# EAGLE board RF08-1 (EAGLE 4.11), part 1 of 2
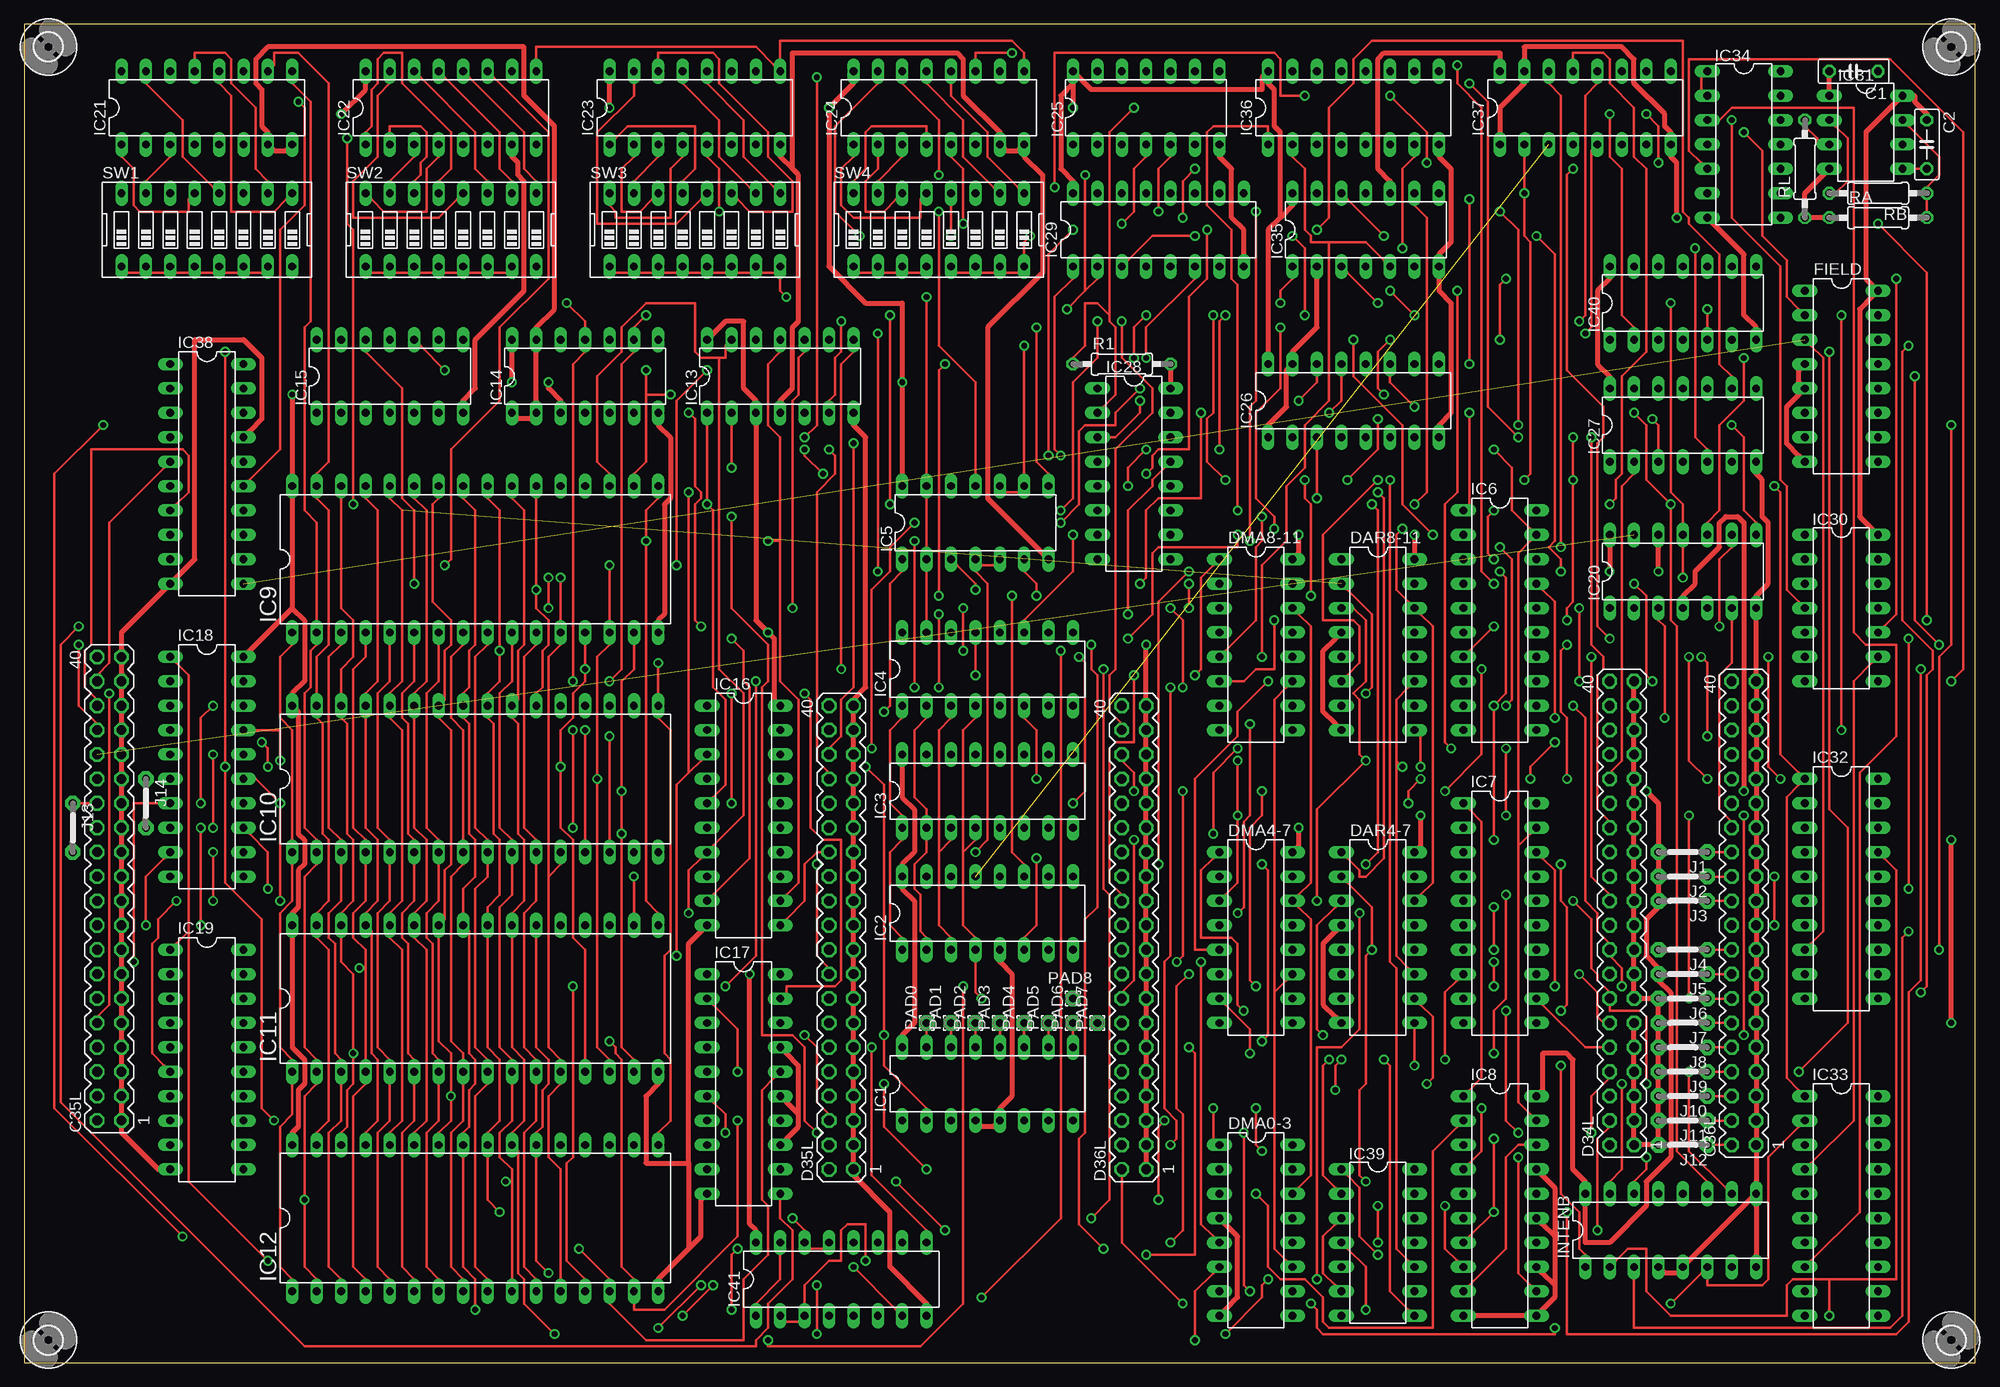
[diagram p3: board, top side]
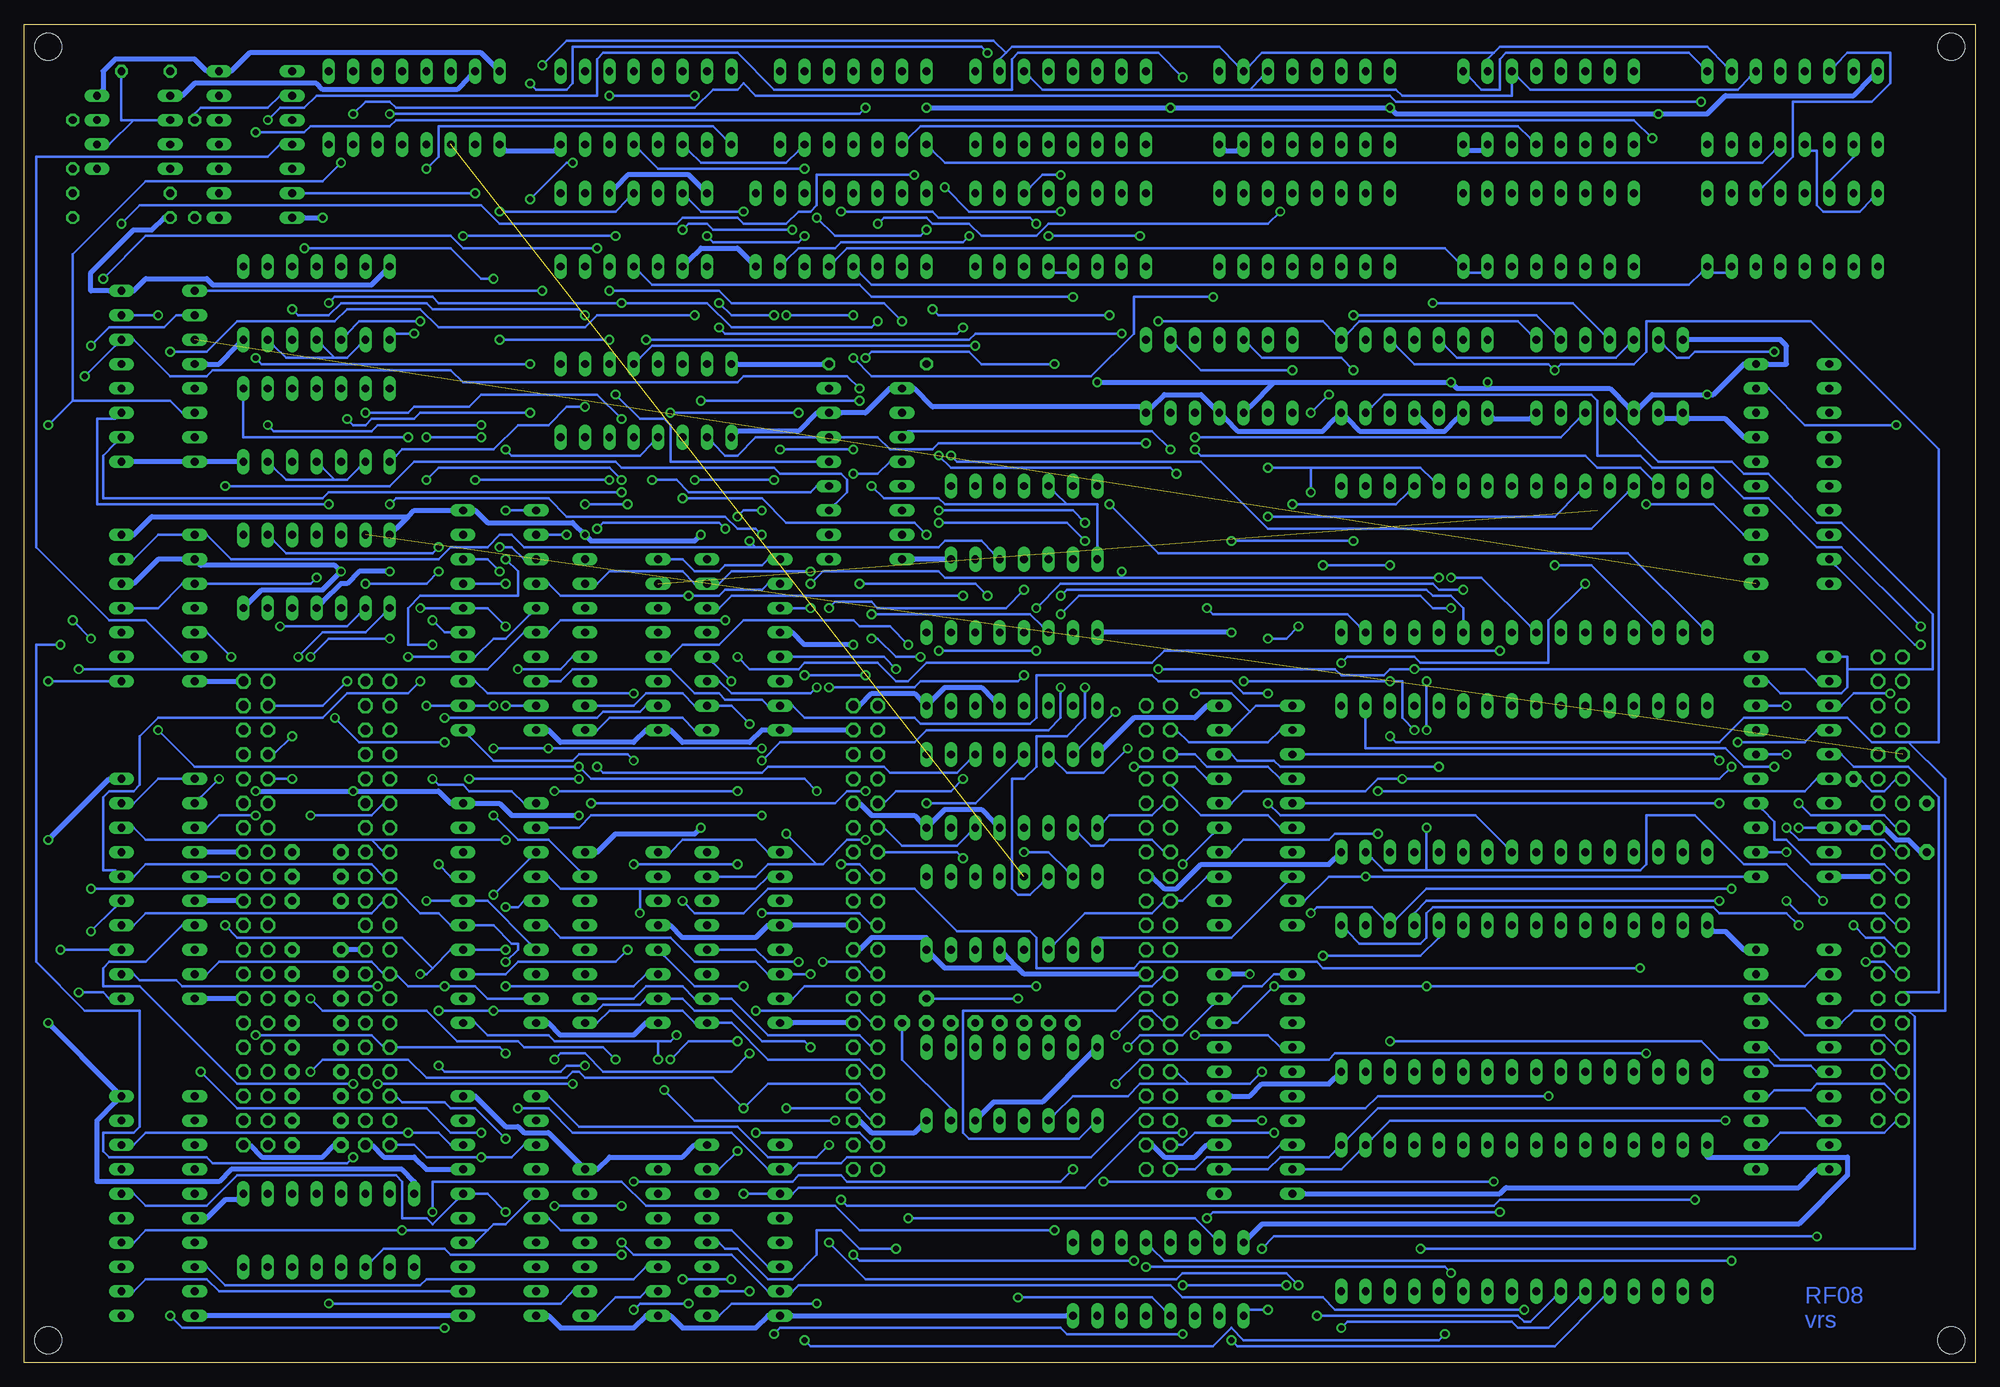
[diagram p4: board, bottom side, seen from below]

Size 203.18 x 139.37 mm. Coordinates in mm from the lower left corner, seen from the top.
Outline: 0,0 203.18,0 203.18,139.37 0,139.37 0,0
Copper layers (1*16): Top 0.035mm / dielectric 1.5mm / Bottom 0.035mm
Design rules "default": minimum track width 10mil, minimum drill 24mil, track to track 8mil, track to pad 8mil, pad to pad 8mil, via to via 8mil, smd to smd 8mil, copper to edge 40mil, drill to drill 8mil, minimum pad ring 10mil, minimum via ring 8mil, stop-mask expansion 4mil, vias tented up to drill 0mil, thermal gap 10mil
Net classes: 1 Power: width 0.508 mm

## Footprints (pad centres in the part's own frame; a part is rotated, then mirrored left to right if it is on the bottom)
C050-025X075 = drill 0.813 octagon: 1 -2.54,0; 2 2.54,0
MA20-2 = drill 1.016 octagon: 1 -24.13,-1.27; 2 -24.13,1.27; 3 -21.59,-1.27; 4 -21.59,1.27; 5 -19.05,-1.27; 6 -19.05,1.27; 7 -16.51,-1.27; 8 -16.51,1.27; 9 -13.97,-1.27; 10 -13.97,1.27; 11 -11.43,-1.27; 12 -11.43,1.27; 13 -8.89,-1.27; 14 -8.89,1.27; 15 -6.35,-1.27; 16 -6.35,1.27; 17 -3.81,-1.27; 18 -3.81,1.27; 19 -1.27,-1.27; 20 -1.27,1.27; 21 1.27,-1.27; 22 1.27,1.27; 23 3.81,-1.27; 24 3.81,1.27; 25 6.35,-1.27; 26 6.35,1.27; 27 8.89,-1.27; 28 8.89,1.27; 29 11.43,-1.27; 30 11.43,1.27; 31 13.97,-1.27; 32 13.97,1.27; 33 16.51,-1.27; 34 16.51,1.27; 35 19.05,-1.27; 36 19.05,1.27; 37 21.59,-1.27; 38 21.59,1.27; 39 24.13,-1.27; 40 24.13,1.27
DIL16 = drill 0.813 long: 1 -8.89,-3.81; 2 -6.35,-3.81; 3 -3.81,-3.81; 4 -1.27,-3.81; 5 1.27,-3.81; 6 3.81,-3.81; 7 6.35,-3.81; 8 8.89,-3.81; 9 8.89,3.81; 10 6.35,3.81; 11 3.81,3.81; 12 1.27,3.81; 13 -1.27,3.81; 14 -3.81,3.81; 15 -6.35,3.81; 16 -8.89,3.81
DIL14 = drill 0.813 long: 1 -7.62,-3.81; 2 -5.08,-3.81; 3 -2.54,-3.81; 4 0,-3.81; 5 2.54,-3.81; 6 5.08,-3.81; 7 7.62,-3.81; 8 7.62,3.81; 9 5.08,3.81; 10 2.54,3.81; 11 0,3.81; 12 -2.54,3.81; 13 -5.08,3.81; 14 -7.62,3.81
DIL20 = drill 0.813 long: 1 -11.43,-3.81; 2 -8.89,-3.81; 3 -6.35,-3.81; 4 -3.81,-3.81; 5 -1.27,-3.81; 6 1.27,-3.81; 7 3.81,-3.81; 8 6.35,-3.81; 9 8.89,-3.81; 10 11.43,-3.81; 11 11.43,3.81; 12 8.89,3.81; 13 6.35,3.81; 14 3.81,3.81; 15 1.27,3.81; 16 -1.27,3.81; 17 -3.81,3.81; 18 -6.35,3.81; 19 -8.89,3.81; 20 -11.43,3.81
DIL32 = drill 0.813 long: 1 -19.05,-7.62; 2 -16.51,-7.62; 3 -13.97,-7.62; 4 -11.43,-7.62; 5 -8.89,-7.62; 6 -6.35,-7.62; 7 -3.81,-7.62; 8 -1.27,-7.62; 9 1.27,-7.62; 10 3.81,-7.62; 11 6.35,-7.62; 12 8.89,-7.62; 13 11.43,-7.62; 14 13.97,-7.62; 15 16.51,-7.62; 16 19.05,-7.62; 17 19.05,7.62; 18 16.51,7.62; 19 13.97,7.62; 20 11.43,7.62; 21 8.89,7.62; 22 6.35,7.62; 23 3.81,7.62; 24 1.27,7.62; 25 -1.27,7.62; 26 -3.81,7.62; 27 -6.35,7.62; 28 -8.89,7.62; 29 -11.43,7.62; 30 -13.97,7.62; 31 -16.51,7.62; 32 -19.05,7.62
DIL08 = drill 0.813 long: 1 -3.81,-3.81; 2 -1.27,-3.81; 3 1.27,-3.81; 4 3.81,-3.81; 5 3.81,3.81; 6 1.27,3.81; 7 -1.27,3.81; 8 -3.81,3.81
05 = drill 0.813 pad 1.6 octagon: 1 -2.54,0; 2 2.54,0
1,6/0,8 = drill 0.813 pad 1.6 octagon: 1 0,0
0207/10 = drill 0.813 octagon: 1 -5.08,0; 2 5.08,0
EDG-08 = drill 0.813 long: 1 -8.89,-3.81; 2 -6.35,-3.81; 3 -3.81,-3.81; 4 -1.27,-3.81; 5 1.27,-3.81; 6 3.81,-3.81; 7 6.35,-3.81; 8 8.89,-3.81; 9 8.89,3.81; 10 6.35,3.81; 11 3.81,3.81; 12 1.27,3.81; 13 -1.27,3.81; 14 -3.81,3.81; 15 -6.35,3.81; 16 -8.89,3.81
2,8 = hole 2.8: 0,0

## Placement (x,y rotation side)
C1  .1uf  [C050-025X075]  190.5,134.46 180 top
C2  .1uf  [C050-025X075]  198.12,126.83 270 top
C35L  [MA20-2]  8.88,49.37 90 top
C36L  [MA20-2]  179.06,46.83 90 top
D34L  [MA20-2]  166.37,46.83 90 top
D35L  [MA20-2]  85.09,44.29 90 top
D36L  [MA20-2]  115.56,44.29 90 top
DAR4-7  74LS193N  [DIL16]  140.97,44.29 270 top
DAR8-11  74LS193N  [DIL16]  140.97,74.77 270 top
DMA0-3  74LS193N  [DIL16]  128.27,13.81 270 top
DMA4-7  74LS193N  [DIL16]  128.27,44.29 270 top
DMA8-11  74LS193N  [DIL16]  128.27,74.77 270 top
FIELD  74LS193N  [DIL16]  189.22,102.7 270 top
IC1  74S138N  [DIL16]  100.33,29.05 0 top
IC2  74S138N  [DIL16]  100.33,46.83 0 top
IC3  74S138N  [DIL16]  100.33,59.52 0 top
IC4  74S138N  [DIL16]  100.33,72.22 0 top
IC5  74LS00N  [DIL14]  99.06,87.46 0 top
IC6  74S240N  [DIL20]  153.66,77.3 270 top
IC7  74S240N  [DIL20]  153.66,46.83 270 top
IC8  74S240N  [DIL20]  153.66,16.35 270 top
IC9  628512  [DIL32]  46.98,83.65 0 top
IC10  628512  [DIL32]  46.98,60.8 0 top
IC11  628512  [DIL32]  46.98,37.94 0 top
IC12  628512  [DIL32]  46.98,15.08 0 top
IC13  74180N  [DIL14]  78.73,102.7 0 top
IC14  74180N  [DIL14]  58.41,102.7 0 top
IC15  74180N  [DIL14]  38.09,102.7 0 top
IC16  74LS244N  [DIL20]  74.93,56.98 270 top
IC17  74LS244N  [DIL20]  74.93,29.05 270 top
IC18  74S240N  [DIL20]  19.05,62.06 270 top
IC19  74S240N  [DIL20]  19.05,31.59 270 top
IC20  74S74N  [DIL14]  172.72,82.38 0 top
IC21  74LS151N  [DIL16]  19.05,130.65 0 top
IC22  74LS151N  [DIL16]  44.45,130.65 0 top
IC23  74LS151N  [DIL16]  69.84,130.65 0 top
IC24  74LS151N  [DIL16]  95.25,130.65 0 top
IC25  74LS20N  [DIL14]  116.84,130.65 0 top
IC26  74S139N  [DIL16]  138.43,100.16 0 top
IC27  7407N  [DIL14]  172.72,97.62 0 top
IC28  74S139N  [DIL16]  115.56,92.54 270 top
IC29  74LS139N  [DIL16]  118.11,117.94 0 top
IC30  74S74N  [DIL14]  189.22,78.57 270 top
IC31  LM555N  [DIL08]  191.77,128.11 270 top
IC32  74S240N  [DIL20]  189.22,49.37 270 top
IC33  74S240N  [DIL20]  189.22,16.35 270 top
IC34  74LS00N  [DIL14]  179.06,126.83 270 top
IC35  74S74N  [DIL14]  139.69,117.94 0 top
IC36  74S139N  [DIL16]  138.43,130.65 0 top
IC37  74LS139N  [DIL16]  162.56,130.65 0 top
IC38  74S240N  [DIL20]  19.05,92.54 270 top
IC39  74S03N  [DIL14]  140.97,12.54 270 top
IC40  7407N  [DIL14]  172.72,110.32 0 top
IC41  74LS139N  [DIL16]  85.09,8.73 0 top
INTENB  74LS193N  [DIL16]  171.44,13.81 0 top
J1  J5MM  [05]  172.72,53.18 180 top
J2  J5MM  [05]  172.72,50.63 180 top
J3  J5MM  [05]  172.72,48.09 180 top
J4  J5MM  [05]  172.72,43.02 180 top
J5  J5MM  [05]  172.72,40.48 180 top
J6  J5MM  [05]  172.72,37.94 180 top
J7  J5MM  [05]  172.72,35.4 180 top
J8  J5MM  [05]  172.72,32.86 180 top
J9  J5MM  [05]  172.72,30.32 180 top
J10  J5MM  [05]  172.72,27.78 180 top
J11  J5MM  [05]  172.72,25.23 180 top
J12  J5MM  [05]  172.72,22.7 180 top
J13  J5MM  [05]  5.08,55.72 270 top
J14  J5MM  [05]  12.69,58.26 270 top
PAD0  [1,6/0,8]  93.98,35.4 90 top
PAD1  [1,6/0,8]  96.52,35.4 90 top
PAD2  [1,6/0,8]  99.06,35.4 90 top
PAD3  [1,6/0,8]  101.59,35.4 90 top
PAD4  [1,6/0,8]  104.14,35.4 90 top
PAD5  [1,6/0,8]  106.68,35.4 90 top
PAD6  [1,6/0,8]  109.22,35.4 90 top
PAD7  [1,6/0,8]  111.76,35.4 90 top
PAD8  [1,6/0,8]  109.22,37.94 90 top
R1  4.7K  [0207/10]  114.3,103.97 0 top
RA  470K  [0207/10]  193.03,119.21 0 top
RB  1.5K  [0207/10]  193.03,121.75 180 top
RL  1K  [0207/10]  185.41,124.29 90 top
SW1  [EDG-08]  19.05,117.94 0 top
SW2  [EDG-08]  44.45,117.94 0 top
SW3  [EDG-08]  69.84,117.94 0 top
SW4  [EDG-08]  95.25,117.94 0 top
U$1  [2,8]  200.66,137 0 top
U$2  [2,8]  2.54,137 0 top
U$3  [2,8]  2.54,2.38 0 top
U$4  [2,8]  200.66,2.38 0 top

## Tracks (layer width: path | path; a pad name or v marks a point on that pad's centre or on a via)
3CYC\
  Top 0.254: C35L.28 6.98,58.26 5.71,58.26 J13.1
601\  (via drill 0.61)
  Top 0.254: v99.06,53.18 100.33,54.45 100.33,81.11 99.06,82.38 IC5.4 99.69,83.02 100.96,83.02 IC5.5 | v128.27,119.85 128.27,100.16 127.63,99.53 v127.63,85.56
  Bottom 0.254: IC30.13 191.77,83.65 189.22,86.19 186.69,86.19 IC30.1 184.15,86.19 181.61,83.65 160.02,83.65 158.75,84.92 154.94,84.92 153.66,86.19 152.4,86.19 151.12,84.92 127,84.92 | v99.06,53.18 96.52,53.18 94.61,51.27 IC2.15 | v128.27,119.85 132.71,119.85 133.98,121.12 IC35.13 | v127.63,85.56 127,84.92 | 127,84.92 107.95,84.92 107.31,85.56 103.5,85.56 102.23,84.29 IC5.5
602\  (via drill 0.61)
  Top 0.254: v89.53,67.78 90.17,68.41 90.17,81.11 91.44,82.38 IC5.1 | v130.81,110.32 130.81,111.59 132.08,112.86 IC35.1 | v125.09,109.05 124.45,108.42 v124.45,95.08 | v116.84,95.08 114.93,93.18 v114.93,91.27
  Bottom 0.254: 94.61,89.37 91.44,89.37 91.44,84.92 IC5.1 | 94.61,89.37 95.88,90.64 IC5.12 | v89.53,67.78 93.34,63.97 IC3.15 | v130.81,110.32 129.53,109.05 v125.09,109.05 | v116.84,95.08 v124.45,95.08 | v114.93,91.27 113.66,90 107.95,90 107.31,89.37 94.61,89.37
604\  (via drill 0.61)
  Top 0.254: IC4.15 93.98,77.3 93.98,82.38 IC5.2 93.98,84.92 93.98,90 IC5.13 93.98,92.54 v93.98,110.96
  Bottom 0.254: v93.98,110.96 114.93,110.96 116.2,112.23 137.79,112.23 139.06,113.5 IC35.4
611\  (via drill 0.61)
  Top 0.254: v92.7,85.56 v92.7,70.32 | v107.95,87.46 109.85,89.37 109.85,96.99 110.48,97.62 113.66,97.62 113.66,98.89 v116.2,101.43 | v168.91,21.43 168.91,20.16 167.63,18.89 INTENB.14 | v199.38,74.77 196.84,77.3 v196.84,102.7
  Bottom 0.254: v92.7,70.32 92.7,67.14 94.61,65.24 97.79,65.24 97.79,62.06 99.06,60.8 100.33,60.8 100.33,49.37 99.69,48.73 98.42,48.73 97.15,50 IC2.14 | v92.7,85.56 94.61,87.46 v107.95,87.46 | v116.2,101.43 117.47,102.7 128.27,102.7 128.9,102.07 157.47,102.07 158.75,103.34 183.51,103.34 184.15,102.7 187.96,102.7 191.77,106.52 FIELD.14 193.67,105.88 v196.84,102.7 | v168.91,21.43 169.54,20.79 183.51,20.79 184.15,21.43 194.31,21.43 194.94,22.06 194.94,23.96 191.77,23.96 191.13,24.6 191.13,36.66 196.84,36.66 201.93,41.74 201.93,74.77 v199.38,74.77
612\  (via drill 0.61)
  Top 0.254: v88.26,63.97 88.26,80.48 90.17,82.38 90.17,84.92 v92.7,87.46 | v107.95,88.73 109.22,90 109.22,102.07 111.76,104.61 v111.76,108.42 | v144.78,109.05 v142.24,111.59 | v175.25,109.69 175.25,107.78 IC40.5
  Bottom 0.254: v88.26,63.97 90.8,61.43 94.61,61.43 95.88,62.7 IC3.14 | v92.7,87.46 93.98,88.73 v107.95,88.73 | v111.76,108.42 113.66,110.32 129.53,110.32 130.81,111.59 v142.24,111.59 | v144.78,109.05 145.41,109.69 160.65,109.69 161.28,110.32 170.18,110.32 171.44,109.05 174.62,109.05 v175.25,109.69
614\  (via drill 0.61)
  Top 0.254: v114.93,77.94 114.93,88.73 117.47,91.27 117.47,91.91 118.74,93.18 IC28.13 | v173.99,116.04 173.99,96.35 175.25,95.08 IC27.5 | v154.3,112.86 153.66,112.23 v153.66,106.52 | v142.24,106.52 140.97,105.24 140.97,101.43 v141.6,100.8
  Bottom 0.254: v114.93,77.94 98.42,77.94 97.15,76.67 IC4.14 | v173.99,116.04 158.75,116.04 155.57,112.86 v154.3,112.86 | v153.66,106.52 v142.24,106.52 | v141.6,100.8 139.06,98.26 136.52,98.26 135.88,97.62 135.88,93.81 120.65,93.81 IC28.13
621\  (1 unrouted)
622\  (via drill 0.61)
  Top 0.254: v109.22,58.26 110.48,59.52 110.48,72.86 v109.85,73.49 | v114.93,75.4 117.47,77.94 117.47,84.29 118.11,84.92 126.36,84.92 v126.36,86.19 | v165.09,89.37 165.73,90 165.73,91.91 166.37,92.54 166.37,102.7 168.91,105.24 168.91,124.29 167.63,125.56 167.63,130.65 165.09,133.19 165.09,135.72 164.46,136.36 161.28,136.36 161.28,135.72 IC37.13
  Bottom 0.254: v109.22,58.26 104.14,58.26 99.69,62.7 IC3.13 | v109.85,73.49 112.39,73.49 114.3,75.4 v114.93,75.4 | v126.36,86.19 127,86.83 128.9,86.83 130.17,88.1 146.68,88.1 148.59,90 164.46,90 v165.09,89.37
624\  (via drill 0.61)
  Top 0.254: v150.49,98.89 150.49,89.37 IC6.1 | v169.54,98.26 170.18,97.62 170.18,95.08 IC27.3 | v99.06,71.59 99.06,74.77 IC4.13 | v119.38,70.32 119.38,42.38 118.74,41.74 118.74,26.51 120.01,25.23 120.01,23.33 v119.38,22.7 | IC7.1 150.49,57.62 151.76,56.35 151.76,29.68 150.49,28.41 IC8.1 | v153.03,88.73 152.4,88.1 152.4,84.29 v153.03,83.65 | v160.65,74.77 160.02,74.13 160.02,67.78 160.65,67.14 v160.65,60.8
  Bottom 0.254: v150.49,98.89 161.92,98.89 162.56,98.26 167,98.26 167.63,97.62 168.91,97.62 v169.54,98.26 | v99.06,71.59 99.69,70.95 109.85,70.95 110.48,70.32 v119.38,70.32 | v119.38,22.7 120.65,21.43 125.73,21.43 128.9,24.6 145.41,24.6 148.59,27.78 IC8.1 | v153.03,88.73 151.12,88.73 IC6.1 | v153.03,83.65 151.76,82.38 151.76,79.84 161.92,79.84 163.19,78.57 163.19,74.77 v160.65,74.77 | v160.65,60.8 160.02,60.16 157.47,60.16 156.84,59.52 152.4,59.52 151.12,58.26 IC7.1
641\  (via drill 0.61)
  Top 0.254: v102.87,79.84 102.87,53.18 104.14,51.91 IC2.11 | v116.2,81.11 116.84,81.75 116.84,88.73 118.11,90 122.55,90 v122.55,98.89 | v135.88,98.89 137.16,100.16 137.16,102.7 IC26.13
  Bottom 0.254: v102.87,79.84 104.14,81.11 v116.2,81.11 | v122.55,98.89 v135.88,98.89
642\  (via drill 0.61)
  Top 0.254: v143.5,62.06 142.87,62.7 | 142.87,62.7 142.87,69.05 144.14,70.32 DAR8-11.11 | 142.87,62.7 142.87,42.38 144.14,41.11 DAR4-7.11
  Bottom 0.254: v143.5,62.06 142.87,61.43 126.36,61.43 125.73,62.06 113.66,62.06 113.03,61.43 106.04,61.43 104.77,62.7 IC3.11
644\  (via drill 0.61)
  Top 0.254: v109.22,86.19 109.22,82.38 104.14,77.3 IC4.11 | v134.62,90 134.62,95.08 IC26.3
  Bottom 0.254: v109.22,86.19 110.48,87.46 123.82,87.46 126.36,90 v134.62,90
645\  (via drill 0.61)
  Top 0.254: 155.57,53.81 155.57,27.14 156.84,25.87 IC8.19 | 155.57,53.81 156.84,55.08 IC7.19 | 155.57,53.81 155.57,84.29 156.84,85.56 IC6.19 156.84,86.83 154.94,88.73 154.94,93.18 v153.03,95.08
  Bottom 0.254: v153.03,95.08 152.4,94.45 139.06,94.45 137.79,95.72 IC26.4
ACB00\  (via drill 0.61)
  Top 0.254: v155.57,21.43 155.57,9.36 156.84,8.09 IC8.12
  Bottom 0.254: IC8.3 151.12,22.7 152.4,21.43 v155.57,21.43 161.28,21.43 162.56,22.7 164.46,22.7 D34L.2 | IC8.12 158.75,7.46 182.88,7.46 184.15,8.73 190.5,8.73 191.77,7.46 IC33.12
ACB01\  (via drill 0.61)
  Top 0.254: v163.83,13.81 163.83,23.33 165.09,24.6 D34L.4
  Bottom 0.254: 154.94,13.81 154.3,14.44 153.03,14.44 150.49,16.98 IC8.5 | 154.94,13.81 156.21,12.54 IC8.14 | 154.94,13.81 v163.83,13.81 190.5,13.81 191.77,12.54 IC33.14
ACB02\  (via drill 0.61)
  Top 0.254: IC8.7 150.49,13.17 v153.03,15.71 v153.03,23.33
  Bottom 0.254: v153.03,15.71 154.94,17.62 156.21,17.62 IC8.16 158.11,16.98 160.65,14.44 161.28,15.08 163.83,15.08 163.83,18.89 164.46,19.52 180.97,19.52 184.15,16.35 190.5,16.35 191.77,17.62 IC33.16 | v153.03,23.33 156.21,26.51 158.75,26.51 159.38,27.14 163.83,27.14 164.46,27.78 D34L.6
ACB03\  (via drill 0.61)
  Top 0.254: IC8.9 150.49,8.09 154.3,11.9 154.3,21.43 155.57,22.7 156.21,22.7 IC8.18 | v163.19,23.96 163.19,27.78 165.09,29.68 D34L.8
  Bottom 0.254: IC33.18 191.77,22.7 190.5,23.96 v163.19,23.96 160.02,23.96 158.75,22.7 IC8.18
ACB04\  (via drill 0.61)
  Top 0.254: v154.3,48.73 154.3,37.94 153.03,36.66 v153.03,32.22 | IC7.12 158.11,37.3 162.56,32.86 164.46,32.86 D34L.10 | v179.06,34.12 v179.06,56.98
  Bottom 0.254: v154.3,48.73 150.49,52.54 IC7.3 | v153.03,32.22 153.66,32.86 164.46,32.86 D34L.10 165.73,32.86 167,34.12 v179.06,34.12 | v179.06,56.98 182.88,56.98 184.15,55.72 IC32.3
ACB05\  (via drill 0.61)
  Top 0.254: v161.92,40.48 163.83,38.57 163.83,36.03 164.46,35.4 D34L.12 | v153.03,43.02 v153.03,47.46 | v182.24,45.55 v182.24,50.63
  Bottom 0.254: 160.65,41.11 161.28,40.48 v161.92,40.48 | 160.65,41.11 158.75,43.02 IC7.14 156.21,43.02 v153.03,43.02 | v153.03,47.46 151.76,47.46 151.12,48.09 IC7.5 | v182.24,50.63 184.15,50.63 IC32.5 | v182.24,45.55 180.97,44.29 163.83,44.29 160.65,41.11
ACB06\  (via drill 0.61)
  Top 0.254: v168.91,29.05 168.91,36.03 168.27,36.66 165.09,36.66 165.09,37.3 D34L.14 165.09,38.57 163.83,39.84 163.83,40.48 163.19,41.11 163.19,46.19 v161.28,48.09
  Bottom 0.254: IC7.7 150.49,43.65 154.94,48.09 156.21,48.09 IC7.16 158.75,48.09 v161.28,48.09 | v168.91,29.05 180.97,29.05 191.13,39.2 194.94,39.2 194.94,41.11 194.31,41.74 190.5,41.74 186.69,45.55 IC32.7
ACB07\  (via drill 0.61)
  Top 0.254: v159.38,39.2 159.38,51.27 158.11,52.54 IC7.18
  Bottom 0.254: IC7.9 151.12,37.94 154.94,37.94 156.21,39.2 v159.38,39.2 163.19,39.2 164.46,40.48 D34L.16 165.73,40.48 167,41.74 182.88,41.74 184.15,40.48 IC32.9
ACB08\  (via drill 0.61)
  Top 0.254: v166.37,39.2 166.37,41.11 165.09,42.38 D34L.18 165.09,43.65 163.83,44.92 163.83,46.83 162.56,48.09 162.56,67.14 v161.28,68.41 | v153.66,84.92 154.94,83.65 154.94,69.05 v154.3,68.41
  Bottom 0.254: v166.37,39.2 186.69,39.2 187.32,39.84 191.13,39.84 191.77,40.48 IC32.12 | v161.28,68.41 158.75,68.41 IC6.12 156.21,68.41 v154.3,68.41 | v153.66,84.92 152.4,84.92 151.12,83.65 IC6.3
ACB09\  (via drill 0.61)
  Top 0.254: v163.19,73.49 163.19,50.63 165.09,48.73 D34L.22
  Bottom 0.254: IC6.5 150.49,77.94 153.03,75.4 154.3,75.4 156.21,73.49 IC6.14 158.75,73.49 v163.19,73.49 | IC32.14 191.77,45.55 190.5,46.83 167,46.83 165.73,48.09 D34L.22
ACB10\  (via drill 0.61)
  Top 0.254: v153.03,76.67 150.49,74.13 IC6.7 | v161.92,70.95 v161.92,78.57
  Bottom 0.254: v153.03,76.67 154.94,78.57 156.21,78.57 IC6.16 158.75,78.57 v161.92,78.57 | D34L.24 165.73,50.63 167,51.91 190.5,51.91 191.77,50.63 IC32.16 193.67,51.27 194.94,51.27 194.94,58.89 194.31,59.52 191.77,59.52 191.13,60.16 191.13,65.24 189.22,67.14 172.08,67.14 169.54,69.68 163.19,69.68 v161.92,70.95
ACB11\  (via drill 0.61)
  Top 0.254: v153.66,82.38 154.3,81.75 154.3,69.68 v153.03,68.41 v153.03,54.45
  Bottom 0.254: v153.03,68.41 151.12,68.41 IC6.9 | v153.66,82.38 154.94,83.65 156.21,83.65 IC6.18 | 167,54.45 190.5,54.45 191.77,55.72 IC32.18 | 167,54.45 165.73,53.18 D34L.26 | v153.03,54.45 167,54.45
ACCLEAR\
  Top 0.254: D34L.32 165.09,61.43 166.37,62.7 166.37,91.27 167.63,92.54 IC27.2
  Bottom 0.254: 170.81,91.91 169.54,91.91 168.27,93.18 IC27.2 | 170.81,91.91 172.08,93.18 IC27.4 | 170.81,91.91 175.89,91.91 177.16,93.18 IC27.6
BAC00  (via drill 0.61)
  Top 0.254: v120.65,6.18 114.3,12.54 114.3,19.52 D36L.2
  Bottom 0.254: v120.65,6.18 129.53,6.18 130.81,4.92 DMA0-3.9
BAC01  (via drill 0.61)
  Top 0.254: v127.63,7.46 127,8.09 v127,23.96
  Bottom 0.254: v127.63,7.46 130.81,7.46 DMA0-3.10 | v127,23.96 116.2,23.96 114.93,22.7 D36L.4
BAC02  (via drill 0.61)
  Top 0.254: v123.82,26.51 123.82,23.33 DMA0-3.1
  Bottom 0.254: v123.82,26.51 116.2,26.51 114.93,25.23 D36L.6
BAC03  (via drill 0.61)
  Top 0.254: v128.9,22.06 128.27,22.7 v128.27,26.51 | v173.35,30.32 173.35,22.06 177.16,18.25 INTENB.10
  Bottom 0.254: v128.9,22.06 130.81,20.16 DMA0-3.15 | D36L.8 114.93,27.78 116.2,29.05 125.73,29.05 v128.27,26.51 131.44,29.68 144.78,29.68 145.41,30.32 146.05,30.32 146.68,29.68 161.28,29.68 163.19,31.59 172.08,31.59 v173.35,30.32
BAC04  (via drill 0.61)
  Top 0.254: v160.02,30.95 160.02,17.62 161.92,15.71 161.92,11.9 162.56,11.27 INTENB.1 | v144.78,30.95 144.78,34.76 DAR4-7.9
  Bottom 0.254: DAR4-7.9 143.5,35.4 142.24,36.66 134.62,36.66 133.34,35.4 DMA4-7.9 130.81,35.4 129.53,35.4 125.73,31.59 116.2,31.59 114.93,30.32 D36L.10 | v160.02,30.95 159.38,30.32 147.31,30.32 146.68,30.95 v144.78,30.95
BAC05  (via drill 0.61)
  Top 0.254: v166.37,29.05 166.37,20.16 165.09,18.89 INTENB.15 | v146.05,29.05 146.68,29.68 146.68,36.03 145.41,37.3 DAR4-7.10
  Bottom 0.254: DAR4-7.10 143.5,37.94 139.69,37.94 138.43,39.2 134.62,39.2 133.34,37.94 DMA4-7.10 130.81,37.94 129.53,37.94 125.73,34.12 116.2,34.12 114.93,32.86 D36L.12 | v146.05,29.05 v166.37,29.05
BAC06  (via drill 0.61)
  Top 0.254: v140.97,90.64 141.6,90 141.6,52.54 139.69,50.63 139.06,50.63 139.06,51.27 137.79,52.54 DAR4-7.1 | v127,36.66 126.36,37.3 126.36,43.65 125.73,44.29 122.55,44.29 122.55,51.27 123.82,52.54 DMA4-7.1
  Bottom 0.254: DMA4-7.1 125.73,53.18 127,54.45 134.62,54.45 135.88,53.18 DAR4-7.1 | v140.97,90.64 171.44,90.64 172.08,90 194.94,90 194.94,94.45 193.67,95.72 FIELD.10 | v127,36.66 116.2,36.66 114.93,35.4 D36L.14
BAC07  (via drill 0.61)
  Top 0.254: v115.56,54.45 115.56,39.84 114.3,38.57 D36L.16 | v154.3,63.97 v154.3,56.98 | v126.36,63.97 123.82,61.43 v123.82,55.08 | v149.22,111.59 149.22,90.64 147.95,89.37 147.95,64.6 v148.59,63.97
  Bottom 0.254: 120.65,51.91 120.01,51.91 117.47,54.45 v115.56,54.45 | 120.65,51.91 125.73,51.91 127,50.63 130.81,50.63 DMA4-7.15 | v154.3,56.98 151.76,54.45 148.59,54.45 145.41,51.27 DAR4-7.15 | v126.36,63.97 v148.59,63.97 v154.3,63.97 | v123.82,55.08 120.65,51.91 | v149.22,111.59 184.15,111.59 FIELD.1
BAC08  (via drill 0.61)
  Top 0.254: v189.22,65.88 v189.22,109.05 | v145.41,62.06 145.41,65.24 DAR8-11.9 | v120.01,41.74 120.65,42.38 v120.65,59.52
  Bottom 0.254: DMA8-11.9 133.34,65.88 134.62,67.14 142.24,67.14 143.5,65.88 DAR8-11.9 | v189.22,109.05 191.77,109.05 FIELD.15 | v189.22,65.88 185.41,62.06 v145.41,62.06 144.14,60.8 121.92,60.8 v120.65,59.52 | v120.01,41.74 116.2,41.74 114.93,40.48 D36L.18
BAC09  (via drill 0.61)
  Top 0.254: v126.36,46.83 127,47.46 127,56.35 127.63,56.98 v127.63,66.51
  Bottom 0.254: DAR8-11.10 143.5,68.41 139.69,68.41 138.43,69.68 134.62,69.68 133.34,68.41 DMA8-11.10 130.81,68.41 129.53,68.41 v127.63,66.51 | v126.36,46.83 116.2,46.83 114.93,45.55 D36L.22
BAC10  (via drill 0.61)
  Top 0.254: v115.56,71.59 115.56,64.6 113.66,64.6 113.03,63.97 113.03,50 114.3,48.73 D36L.24 | v121.92,71.59 122.55,72.22 122.55,81.75 123.82,83.02 DMA8-11.1
  Bottom 0.254: DMA8-11.1 125.73,83.65 126.36,83.02 130.17,83.02 130.81,82.38 133.34,82.38 134.62,83.65 135.88,83.65 DAR8-11.1 | v115.56,71.59 v121.92,71.59
BAC11  (via drill 0.61)
  Top 0.254: v118.11,51.91 118.11,79.21 v121.28,82.38
  Bottom 0.254: DAR8-11.15 143.5,81.11 142.24,82.38 134.62,82.38 133.34,81.11 DMA8-11.15 130.81,81.11 129.53,82.38 v121.28,82.38 | v118.11,51.91 116.2,51.91 114.93,50.63 D36L.26
BADDAC\  (via drill 0.61)
  Top 0.254: v174.62,73.49 175.25,72.86 v175.25,65.24
  Bottom 0.254: v174.62,73.49 172.08,76.03 167.63,76.03 165.73,77.94 IC20.1 | v175.25,65.24 177.16,63.34 C36L.34
BBREAK\  (via drill 0.61)
  Top 0.254: IC41.1 76.2,6.18 78.73,8.73 78.73,11.27 IC41.15 | v128.9,88.1 128.9,85.56 128.27,84.92 128.27,77.3 125.09,74.13 DMA8-11.5 | v126.36,88.73 126.36,112.23 125.73,112.86 125.73,117.94 123.19,120.48 123.19,128.11 123.82,128.74 129.53,128.74 129.53,128.11 IC36.1 | v175.25,60.8 173.35,62.7 v173.35,73.49 | v165.09,75.4 163.83,76.67 163.83,95.72 164.46,96.35 164.46,99.53 160.65,103.34 160.65,123.66 v161.28,124.29 | v111.12,15.08 113.03,16.98 113.03,48.73 112.39,49.37 v112.39,72.22 | v8.25,97.62 3.17,92.54 3.17,26.51 v16.51,13.17 | v74.29,11.9 73.66,11.27 v73.66,5.55
  Bottom 0.254: v128.9,88.1 128.27,88.73 v126.36,88.73 | v175.25,60.8 177.16,60.8 C36L.32 | v173.35,73.49 171.44,75.4 v165.09,75.4 | v161.28,124.29 160.02,125.56 160.02,128.74 131.44,128.74 130.17,127.47 IC36.1 | v111.12,15.08 81.28,15.08 79.37,13.17 IC41.15 | v112.39,72.22 113.66,73.49 123.19,73.49 DMA8-11.5 | v8.25,97.62 17.78,97.62 21.59,101.43 IC38.19 | v16.51,13.17 73.02,13.17 v74.29,11.9 | v73.66,5.55 75.56,5.55 IC41.1
BINIT  (via drill 0.61)
  Top 0.254: v172.72,81.75 172.72,84.92 IC20.11 172.72,87.46 172.72,89.37 171.44,90.64 v171.44,110.32 | v140.97,110.32 137.79,113.5 IC35.3 | v114.3,108.42 114.3,104.61 117.47,101.43 117.47,98.89 113.66,95.08 113.66,72.22 113.03,71.59 113.03,67.78 114.3,66.51 D36L.38
  Bottom 0.254: IC30.11 191.77,78.57 189.22,78.57 186.69,81.11 IC30.3 184.15,81.11 173.35,81.11 v172.72,81.75 | v171.44,110.32 170.81,110.96 160.65,110.96 160.02,110.32 v140.97,110.32 132.08,110.32 129.53,107.78 114.93,107.78 v114.3,108.42
BINIT\  (via drill 0.61)
  Top 0.254: v141.6,117.31 137.79,121.12 IC35.12 | v157.47,117.31 159.38,115.4 159.38,85.56 158.75,84.92 160.02,83.65 v160.02,82.38 | v167.63,81.11 168.91,79.84 168.91,71.59 v169.54,70.95
  Bottom 0.254: v141.6,117.31 v157.47,117.31 | v160.02,82.38 161.28,81.11 v167.63,81.11 | v169.54,70.95 172.08,68.41 177.16,68.41 C36L.38
BIOP1  (via drill 0.61)
  Top 0.254: v105.41,52.54 105.41,45.55 104.14,44.29 IC2.6
  Bottom 0.254: v105.41,52.54 106.04,53.18 113.66,53.18 D36L.28
BIOP2
  Bottom 0.254: IC3.6 104.77,55.08 106.04,53.81 111.76,53.81 113.66,55.72 D36L.30
BIOP4  (via drill 0.61)
  Top 0.254: v105.41,60.8 105.41,65.88 104.14,67.14 IC4.6
  Bottom 0.254: v105.41,60.8 106.68,59.52 112.39,59.52 113.66,58.26 D36L.32
BMB00
  Bottom 0.254: IC17.8 72.39,22.7 73.66,21.43 80.01,21.43 81.28,20.16 83.18,20.16 D35L.2
BMB01  (via drill 0.61)
  Top 0.254: v73.02,23.96 73.02,25.87 71.75,27.14 IC17.6
  Bottom 0.254: v73.02,23.96 81.28,23.96 82.55,22.7 83.18,22.7 D35L.4
BMB02  (via drill 0.61)
  Top 0.254: v81.28,34.12 82.55,32.86 82.55,27.14 83.81,25.87 D35L.6
  Bottom 0.254: v81.28,34.12 73.66,34.12 72.39,32.86 IC17.4
BMB03  (via drill 0.61)
  Top 0.254: v74.29,30.32 74.29,34.76 71.75,37.3 IC17.2
  Bottom 0.254: v74.29,30.32 75.56,29.05 81.91,29.05 | 81.91,29.05 83.18,30.32 D35L.10 | 81.91,29.05 86.99,29.05 88.26,27.78 93.98,27.78 95.88,25.87 IC1.3
BMB04  (via drill 0.61)
  Top 0.254: IC1.2 93.98,26.51 89.53,30.95 v89.53,34.12 89.53,60.16 v87.62,62.06
  Bottom 0.254: v89.53,34.12 86.99,36.66 85.72,36.66 84.45,35.4 D35L.14 | v87.62,62.06 81.28,62.06 80.01,60.8 IC16.17
BMB05  (via drill 0.61)
  Top 0.254: v82.55,51.91 82.55,42.38 83.81,41.11 D35L.18
  Bottom 0.254: IC1.1 92.07,24.6 93.34,23.33 104.77,23.33 105.41,23.96 105.41,36.66 89.53,36.66 86.99,39.2 85.72,39.2 84.45,40.48 D35L.18 | v82.55,51.91 79.37,55.08 IC16.15
BMB06
  Top 0.254: 95.25,53.18 95.25,45.55 96.52,44.29 IC2.3 | 95.25,53.18 96.52,54.45 IC3.3 | 95.25,53.18 95.25,65.88 96.52,67.14 IC4.3
  Bottom 0.254: IC16.13 80.01,50.63 82.55,48.09 83.18,48.09 D35L.24 84.45,48.09 85.72,46.83 92.7,46.83 95.88,43.65 IC2.3
BMB07
  Top 0.254: IC16.11 79.37,46.19 81.28,48.09 81.28,51.91 82.55,53.18 83.18,53.18 D35L.28 | IC2.2 93.98,44.29 93.34,44.92 93.34,48.73 92.7,49.37 92.7,51.91 93.98,53.18 93.98,54.45 IC3.2 93.98,56.98 93.98,57.62 92.7,58.89 92.7,65.88 93.98,67.14 IC4.2
  Bottom 0.254: D35L.28 84.45,53.18 85.72,54.45 90.17,54.45 90.8,53.81 92.07,53.81 93.34,55.08 IC3.2
BMB08
  Top 0.254: IC4.1 91.44,67.14 90.17,65.88 90.17,58.26 91.44,56.98 IC3.1 91.44,54.45 90.17,53.18 90.17,45.55 91.44,44.29 IC2.1
  Bottom 0.254: IC3.1 90.8,56.35 90.17,56.98 85.72,56.98 84.45,58.26 D35L.32 | IC16.8 71.75,50 77.47,44.29 91.44,44.29 IC2.1
BMB09  (via drill 0.61)
  Top 0.254: v116.2,100.16 116.2,98.89 113.66,96.35 113.03,96.35 IC28.3 | v132.71,100.16 134.62,102.07 134.62,102.7 IC26.14 | v83.81,95.08 84.45,94.45 84.45,92.54 82.55,90.64 82.55,62.7 83.81,61.43 D35L.34
  Bottom 0.254: IC16.6 72.39,55.72 73.66,56.98 80.64,56.98 83.81,60.16 D35L.34 | v116.2,100.16 v132.71,100.16 | v83.81,95.08 85.72,96.99 111.12,96.99 IC28.3
BMB10  (via drill 0.61)
  Top 0.254: v86.36,95.72 86.36,70.32 85.09,69.05 85.09,65.24 83.81,63.97 D35L.36
  Bottom 0.254: IC26.2 131.44,95.72 130.17,94.45 128.9,94.45 127,96.35 120.65,96.35 IC28.14 118.11,96.35 114.3,96.35 113.03,95.08 108.58,95.08 107.95,95.72 v86.36,95.72 | IC16.4 72.39,60.8 73.66,62.06 80.01,62.06 81.28,63.34 83.18,63.34 D35L.36
BMB11
  Bottom 0.254: IC16.2 72.39,65.88 73.66,64.6 81.91,64.6 83.18,65.88 D35L.38
BRK_RQ\
  Top 0.254: IC20.6 177.8,77.3 177.8,72.86 176.53,71.59 176.53,57.62 177.8,56.35 C36L.28
BTS1  (via drill 0.61)
  Top 0.254: v170.81,67.14 170.81,76.67 170.18,77.3 IC20.3 | v159.38,64.6 156.84,62.06 v156.84,60.8 | v145.41,60.8 144.14,59.52 v144.14,58.26 | v115.56,59.52 115.56,61.43 114.3,62.7 D36L.36
  Bottom 0.254: v170.81,67.14 168.27,64.6 v159.38,64.6 | v145.41,60.8 v156.84,60.8 | v144.14,58.26 118.74,58.26 117.47,59.52 v115.56,59.52
BUSY  (via drill 0.61)
  Top 0.254: v176.53,76.67 176.53,83.65 177.8,84.92 IC20.9 | v160.02,84.92 160.02,131.92 158.75,133.19 IC37.14
  Bottom 0.254: v176.53,76.67 169.54,76.67 168.27,77.94 IC20.2 | v160.02,84.92 160.65,84.29 175.89,84.29 177.16,85.56 IC20.9
BWCO\  (1 unrouted)
CA_INCR\
  Bottom 0.254: C35L.30 8.25,60.8 9.52,59.52 10.79,59.52 12.06,60.8 J14.1
CIE  (via drill 0.61)
  Top 0.254: v140.97,11.27 139.06,13.17 139.06,18.25 137.79,19.52 IC39.1 | v196.21,44.92 195.58,44.29 195.58,4.92 194.31,3.65 167.63,3.65 167.63,8.73 INTENB.3
  Bottom 0.254: v140.97,11.27 158.75,11.27 159.38,11.9 165.73,11.9 167,10.63 INTENB.3 | v196.21,44.92 193.67,47.46 IC32.15
DA00\
  Top 0.254: C36L.2 177.16,22.7 175.89,22.7 J12.1
DA01\
  Top 0.254: C36L.4 177.16,25.23 175.89,25.23 J11.1
DA02\
  Top 0.254: C36L.6 177.16,27.78 175.89,27.78 J10.1
DA03\
  Top 0.254: C36L.8 177.16,30.32 175.89,30.32 J9.1
DA04\
  Top 0.254: C36L.10 177.16,32.86 175.89,32.86 J8.1
DA05\
  Top 0.254: C36L.12 177.16,35.4 175.89,35.4 J7.1
DA06\
  Top 0.254: C36L.14 177.16,37.94 175.89,37.94 J6.1
DA07\
  Top 0.254: C36L.16 177.16,40.48 175.89,40.48 J5.1
DA08\
  Top 0.254: C36L.18 177.16,43.02 175.89,43.02 J4.1
DA09\
  Top 0.254: C36L.22 177.16,48.09 175.89,48.09 J3.1
DA10\
  Top 0.254: C36L.24 177.16,50.63 175.89,50.63 J2.1
DA11\
  Top 0.254: C36L.26 177.16,53.18 175.89,53.18 J1.1
DAR04  (via drill 0.61)
  Top 0.254: IC41.2 79.37,4.28 80.64,4.28 IC41.3 81.28,6.18 81.28,8.09 83.81,10.63 85.09,10.63 85.09,13.81 85.72,14.44 87.62,14.44 v87.62,10.63 | v160.02,36.66 160.65,37.3 160.65,47.46 160.02,48.09 v160.02,51.91 | v121.92,117.31 117.47,117.31 114.93,114.77 IC29.3 | v132.08,117.31 133.34,116.04 v133.34,109.05 | v187.96,105.24 187.96,57.62 189.86,55.72 189.86,35.4 v184.78,30.32 | v155.57,23.96 154.3,25.23 v154.3,36.66 | v116.84,11.27 121.92,11.27 121.92,32.22 v121.28,32.86
  Bottom 0.254: v160.02,36.66 v154.3,36.66 143.5,36.66 142.87,37.3 139.06,37.3 138.43,37.94 DAR4-7.7 135.88,37.94 134.62,37.94 133.34,36.66 129.53,36.66 126.36,33.49 121.92,33.49 v121.28,32.86 | v160.02,51.91 158.75,50.63 IC7.17 | v121.92,117.31 122.55,116.67 131.44,116.67 v132.08,117.31 | v133.34,109.05 143.5,109.05 144.78,107.78 160.02,107.78 161.92,109.69 169.54,109.69 170.81,108.42 180.97,108.42 184.15,105.24 v187.96,105.24 | v184.78,30.32 180.97,26.51 161.28,26.51 158.75,23.96 v155.57,23.96 | v87.62,10.63 116.2,10.63 v116.84,11.27
DAR05  (via drill 0.61)
  Top 0.254: v153.03,41.74 v153.03,39.2 | IC12.1 27.94,8.73 26.67,10 26.67,24.6 27.94,25.87 27.94,29.05 IC11.1 27.94,31.59 26.67,32.86 26.67,46.83 27.94,48.09 27.94,51.91 IC10.1 27.94,54.45 27.94,65.88 26.67,67.14 26.67,73.49 27.94,74.77 IC9.1 | 110.48,111.59 v108.58,109.69 | 110.48,111.59 111.76,112.86 IC29.2 | v90.17,109.05 v90.17,89.37 | v196.21,75.4 v196.21,49.37 | v198.12,77.3 198.12,113.5 v193.03,118.58 | v110.48,123.66 110.48,111.59
  Bottom 0.254: v153.03,39.2 139.69,39.2 138.43,40.48 DAR4-7.6 | v153.03,41.74 151.76,43.02 151.76,43.65 152.4,43.65 154.3,45.55 156.21,45.55 IC7.15 158.75,45.55 160.02,46.83 161.92,46.83 164.46,49.37 v196.21,49.37 | v108.58,109.69 107.95,109.05 v90.17,109.05 | v90.17,89.37 85.09,84.29 36.19,84.29 28.57,76.67 IC9.1 | v198.12,77.3 v196.21,75.4 | v193.03,118.58 191.13,120.48 155.57,120.48 153.66,118.58 135.25,118.58 134.62,119.21 128.9,119.21 128.27,118.58 123.82,118.58 122.55,119.85 121.28,119.85 120.65,120.48 120.65,123.66 v110.48,123.66
DAR06  (via drill 0.61)
  Top 0.254: DAR4-7.2 137.79,50 140.33,47.46 v140.33,43.02 139.69,42.38 139.69,29.05 139.06,28.41 139.06,19.52 v139.69,18.89 | IC12.30 33.02,23.96 33.65,24.6 33.65,28.41 34.28,29.05 v34.28,32.22 34.28,40.48 33.02,41.74 33.02,44.29 IC11.30 33.02,46.83 34.28,48.09 34.28,54.45 33.65,55.08 33.65,66.51 33.02,67.14 IC10.30 33.02,69.68 33.02,72.22 34.28,73.49 34.28,77.3 33.02,78.57 33.02,90 IC9.30 | v107.95,94.45 107.31,95.08 107.31,110.96 109.22,112.86 IC29.1 | v83.18,92.54 81.28,94.45 v81.28,95.08 | v93.98,20.16 89.53,24.6 v89.53,29.05
  Bottom 0.254: v140.33,43.02 141.6,41.74 151.76,41.74 153.03,40.48 156.21,40.48 IC7.13 | v107.95,94.45 106.68,93.18 83.81,93.18 v83.18,92.54 | v81.28,95.08 80.64,94.45 40.63,94.45 39.36,93.18 34.92,93.18 33.65,91.91 IC9.30 | v139.69,18.89 123.19,18.89 122.55,19.52 118.11,19.52 117.47,18.89 95.25,18.89 v93.98,20.16 | v89.53,29.05 86.99,31.59 67.31,31.59 66.67,32.22 v34.28,32.22
DAR07  (via drill 0.61)
  Top 0.254: IC22.9 53.34,135.72 53.34,137 76.2,137 78.1,135.09 IC23.9 78.73,135.72 78.73,137.63 102.87,137.63 104.14,136.36 104.14,135.72 IC24.9 | v135.25,34.12 134.62,34.76 134.62,45.55 136.52,47.46 DAR4-7.3 | IC12.2 30.48,8.73 29.21,10 v29.21,16.98 29.21,27.78 30.48,29.05 IC11.2 30.48,31.59 29.21,32.86 29.21,50.63 30.48,51.91 IC10.2 30.48,54.45 29.21,55.72 29.21,69.68 29.84,70.32 29.84,74.13 30.48,74.77 IC9.2 30.48,77.3 30.48,87.46 29.21,88.73 29.21,107.78 29.84,108.42 29.84,131.28 27.94,133.19 IC21.9 | v137.16,31.59 136.52,30.95 v136.52,28.41 | v118.74,25.23 118.11,24.6 v118.11,16.98
  Bottom 0.254: IC21.9 28.57,135.09 29.84,136.36 48.89,136.36 49.52,135.72 49.52,132.55 51.43,132.55 52.7,133.82 IC22.9 | 137.16,33.49 135.88,33.49 v135.25,34.12 | 137.16,33.49 147.95,33.49 148.59,34.12 154.94,34.12 156.21,35.4 IC7.11 | v137.16,31.59 137.16,33.49 | v136.52,28.41 133.34,25.23 v118.74,25.23 | v118.11,16.98 117.47,16.35 50.16,16.35 49.52,16.98 v29.21,16.98
DAR08  (via drill 0.61)
  Top 0.254: IC12.31 30.48,23.96 31.75,25.23 31.75,43.02 30.48,44.29 IC11.31 30.48,46.83 31.75,48.09 31.75,54.45 31.11,55.08 31.11,66.51 30.48,67.14 IC10.31 30.48,69.68 30.48,73.49 31.75,74.77 31.75,88.73 30.48,90 IC9.31 30.48,92.54 31.75,93.81 31.75,133.19 28.57,136.36 26.03,136.36 26.03,135.09 IC21.10 | v159.38,67.14 159.38,79.21 158.11,80.48 IC6.17 | v153.03,81.11 151.76,82.38 151.76,130.65 149.22,133.19 v149.22,135.09
  Bottom 0.254: v159.38,67.14 143.5,67.14 142.87,67.78 139.06,67.78 138.43,68.41 DAR8-11.7 | 50.16,136.36 50.79,135.72 IC22.10 | 50.16,136.36 49.52,137 27.94,137 26.03,135.09 IC21.10 | 50.16,136.36 74.29,136.36 75.56,135.09 IC23.10 76.83,135.09 78.73,137 100.33,137 100.96,136.36 | 100.96,136.36 101.59,135.72 IC24.10 | v153.03,81.11 156.21,81.11 IC6.17 | v149.22,135.09 146.68,137.63 102.23,137.63 100.96,136.36
DAR09  (via drill 0.61)
  Top 0.254: IC12.3 33.02,8.73 31.75,10 31.75,23.96 33.02,25.23 33.02,29.05 IC11.3 33.02,31.59 32.38,32.22 32.38,43.65 31.75,44.29 31.75,46.83 33.02,48.09 33.02,51.91 IC10.3 33.02,54.45 31.75,55.72 31.75,73.49 33.02,74.77 IC9.3 | v140.97,91.91 135.25,86.19 135.25,77.3 138.43,77.3 139.06,76.67 139.06,72.86 137.79,71.59 DAR8-11.6 | v160.65,77.3 160.65,78.57 161.28,79.21 v161.28,91.91 v161.28,96.35 | v155.57,96.35 152.4,99.53 152.4,131.28 v150.49,133.19 | v102.87,136.36 99.06,136.36 99.06,135.72 IC24.11 | v43.81,83.02 44.45,83.65 44.45,95.08 49.52,100.16 49.52,107.78 54.6,112.86 54.6,128.11 48.89,133.82 IC22.11
  Bottom 0.254: v140.97,91.91 142.24,93.18 160.02,93.18 v161.28,91.91 | v160.65,77.3 159.38,76.03 158.75,76.03 IC6.15 | IC21.11 23.49,133.82 24.76,132.55 46.35,132.55 47.62,133.82 IC22.11 48.25,133.19 48.25,131.92 59.68,131.92 60.32,132.55 75.56,132.55 | 75.56,132.55 74.29,133.82 IC23.11 | 75.56,132.55 97.15,132.55 98.42,133.82 IC24.11 | v161.28,96.35 v155.57,96.35 | v150.49,133.19 149.86,132.55 146.68,132.55 146.05,133.19 146.05,137 103.5,137 v102.87,136.36 | v43.81,83.02 40,83.02 33.65,76.67 IC9.3
DAR10  (via drill 0.61)  (1 unrouted)
  Top 0.254: IC12.28 38.09,23.96 39.36,25.23 39.36,43.02 38.09,44.29 IC11.28 38.09,46.83 39.36,48.09 39.36,65.88 38.09,67.14 IC10.28 38.09,69.68 39.36,70.95 39.36,88.73 38.09,90 IC9.28 | v139.69,69.68 140.33,70.32 140.33,77.94 137.79,80.48 DAR8-11.2
  Bottom 0.254: v139.69,69.68 154.94,69.68 156.21,70.95 IC6.13
DAR11  (via drill 0.61)
  Top 0.254: DAR8-11.3 138.43,78.57 139.69,77.3 139.69,70.95 138.43,69.68 139.06,69.05 139.06,63.34 v139.69,62.7 134.62,57.62 v134.62,48.09 | IC12.4 35.55,8.73 34.28,10 34.28,27.78 35.55,29.05 IC11.4 35.55,31.59 35.55,41.11 | IC9.4 35.55,74.77 35.55,73.49 34.28,72.22 34.28,55.72 35.55,54.45 IC10.4 35.55,51.91 35.55,48.09 34.28,46.83 34.28,44.29 35.55,43.02 35.55,41.11 | 35.55,41.11 v34.92,41.11
  Bottom 0.254: v139.69,62.7 140.33,63.34 145.41,63.34 146.05,62.7 154.3,62.7 156.84,65.24 IC6.11 | v134.62,48.09 133.34,46.83 128.27,46.83 125.73,49.37 110.48,49.37 106.04,44.92 98.42,44.92 97.79,44.29 97.79,41.11 87.62,41.11 86.99,41.74 68.58,41.74 67.94,41.11 v34.92,41.11
DATA00\
  Bottom 0.254: IC19.12 21.59,22.7 20.32,23.96 9.52,23.96 8.25,25.23 C35L.2
DATA01\
  Bottom 0.254: IC19.14 21.59,27.78 20.95,28.41 17.14,28.41 16.51,29.05 9.52,29.05 8.25,27.78 C35L.4
DATA02\
  Bottom 0.254: IC19.16 21.59,32.86 20.32,31.59 9.52,31.59 8.25,30.32 C35L.6
DATA03\
  Bottom 0.254: IC19.18 21.59,37.94 17.78,34.12 9.52,34.12 8.25,32.86 C35L.8
DATA04\  (via drill 0.61)
  Top 0.254: v8.88,69.68 8.88,37.3 7.62,36.03 C35L.10
  Bottom 0.254: v8.88,69.68 12.69,69.68 13.96,68.41 IC18.3
DATA05\
  Bottom 0.254: IC18.5 13.96,63.34 12.69,62.06 6.98,62.06 3.81,58.89 3.81,38.57 7.62,38.57 C35L.12
DATA06\  (via drill 0.61)
  Top 0.254: v11.42,41.74 11.42,58.26 13.96,58.26 IC18.7
  Bottom 0.254: v11.42,41.74 9.52,41.74 8.25,40.48 C35L.14
DATA07\  (via drill 0.61)
  Top 0.254: v12.69,45.55 12.69,50.63 14.6,52.54 IC18.9
  Bottom 0.254: v12.69,45.55 11.42,44.29 9.52,44.29 8.25,43.02 C35L.16
DATA08\  (via drill 0.61)
  Top 0.254: v19.68,48.09 v19.68,53.18
  Bottom 0.254: v19.68,53.18 21.59,53.18 IC18.12 | v19.68,48.09 18.41,46.83 9.52,46.83 8.25,45.55 C35L.18
DATA09\
  Bottom 0.254: IC18.14 22.22,57.62 20.95,56.35 20.95,54.45 19.68,54.45 17.14,51.91 9.52,51.91 8.25,50.63 C35L.22
DATA10\  (via drill 0.61)
  Top 0.254: v19.68,55.72 v19.68,63.34
  Bottom 0.254: v19.68,63.34 21.59,63.34 IC18.16 | v19.68,55.72 18.41,54.45 9.52,54.45 8.25,53.18 C35L.24
DATA11\  (via drill 0.61)
  Top 0.254: v19.68,68.41 18.41,67.14 v18.41,58.26
  Bottom 0.254: v19.68,68.41 21.59,68.41 IC18.18 | v18.41,58.26 17.14,56.98 9.52,56.98 8.25,55.72 C35L.26
DCXA\  (via drill 0.61)
  Top 0.254: IC5.10 102.23,90.64 103.5,90.64 IC5.9 104.14,92.54 v104.14,105.88
  Bottom 0.254: v104.14,105.88 137.79,105.88 139.06,104.61 IC26.12
DIMA\  (via drill 0.61)
  Top 0.254: IC33.1 184.78,28.41 183.51,29.68 183.51,58.89 184.78,60.16 IC32.1 184.78,61.43 182.88,63.34 182.88,90.64 v182.24,91.27
  Bottom 0.254: v182.24,91.27 165.09,91.27 162.56,93.81 141.6,93.81 140.97,93.18 125.09,93.18 124.45,92.54 118.11,92.54 117.47,91.91 117.47,90.64 118.74,89.37 IC28.11 | IC32.19 191.77,58.26 189.22,60.8 186.69,60.8 IC32.1
DIML\  (via drill 0.61)
  Top 0.254: INTENB.11 175.25,18.89 172.08,22.06 172.08,76.67 171.44,77.3 v171.44,89.37 168.91,91.91 168.91,97.62 v167.63,98.89 | v137.79,91.91 140.97,95.08 v140.97,98.26
  Bottom 0.254: v171.44,89.37 195.58,89.37 195.58,98.26 193.67,98.26 FIELD.11 | v137.79,91.91 135.25,91.91 133.98,90.64 121.28,90.64 120.65,91.27 IC28.12 | v140.97,98.26 143.5,100.8 155.57,100.8 156.84,99.53 162.56,99.53 163.19,98.89 v167.63,98.89
DIO00  (via drill 0.61)
  Top 0.254: IC12.17 66.04,23.96 67.31,25.23 67.31,31.59 66.67,32.22 66.67,42.38 67.31,43.02 67.31,65.88 66.04,67.14 IC10.17 66.04,69.68 v66.04,72.86 | v40.63,81.11 40.63,88.73 39.36,90 39.36,101.43 35.55,105.24 IC15.12
  Bottom 0.254: IC15.12 36.19,105.88 37.46,104.61 53.97,104.61 55.24,105.88 IC14.12 | IC17.12 77.47,20.16 73.66,20.16 72.39,21.43 67.31,21.43 66.67,22.06 IC12.17 65.4,23.33 62.22,26.51 17.78,26.51 16.51,25.23 IC19.8 | v40.63,81.11 44.45,77.3 44.45,72.86 57.78,72.86 58.41,73.49 65.4,73.49 v66.04,72.86
DIO01  (via drill 0.61)
  Top 0.254: v56.51,110.32 58.41,108.42 58.41,107.78 IC14.11 58.41,105.24 57.14,103.97 v57.14,70.95 | v60.95,33.49 61.59,32.86 61.59,32.22 62.22,31.59 62.22,10 63.49,8.73 IC12.15 63.49,6.18 63.49,5.55 66.67,5.55 74.29,13.17 v74.29,25.23 | v15.87,48.09 13.96,46.19 13.96,44.29 13.33,43.65 13.33,32.22 14.6,30.95 IC19.6 | v57.14,55.72 v57.14,65.88
  Bottom 0.254: v56.51,110.32 41.9,110.32 38.73,107.15 IC15.11 | v60.95,33.49 28.57,33.49 26.67,31.59 21.59,31.59 20.95,30.95 17.14,30.95 16.51,30.32 IC19.6 | v74.29,25.23 77.47,25.23 IC17.14 | 57.14,51.27 34.92,51.27 34.28,51.91 34.28,56.98 29.21,56.98 24.12,51.91 19.68,51.91 v15.87,48.09 | 57.14,51.27 61.59,51.27 62.86,52.54 IC10.15 | v57.14,65.88 v57.14,70.95 | 57.14,51.27 v57.14,55.72
DIO02  (via drill 0.61)
  Top 0.254: v43.81,103.34 41.27,105.88 IC15.10 | IC17.16 78.1,29.68 76.83,28.41 76.83,16.98 77.47,16.35 77.47,11.27 74.93,8.73 74.93,2.38 64.77,2.38 60.95,6.18 IC12.14 60.95,8.73 v57.78,11.9 | v60.95,65.24 60.95,54.45 IC10.14
  Bottom 0.254: IC14.10 60.32,105.88 58.41,103.97 44.45,103.97 v43.81,103.34 43.17,103.97 35.55,103.97 34.28,105.24 34.28,108.42 17.14,108.42 3.81,95.08 3.81,64.6 6.98,64.6 | 6.98,36.66 12.69,36.66 13.96,35.4 IC19.4 | 6.98,36.66 6.34,36.03 6.34,11.9 v57.78,11.9 | v60.95,65.24 60.32,64.6 26.67,64.6 24.12,67.14 13.33,67.14 10.79,64.6 6.98,64.6 | 6.98,64.6 3.17,60.8 3.17,36.66 6.98,36.66
DIO03  (via drill 0.61)
  Top 0.254: v58.41,65.88 58.41,54.45 IC10.13 | v60.95,70.95 62.22,72.22 62.22,103.97 63.49,105.24 IC14.9 63.49,107.78 v64.77,109.05 | v57.14,39.2 57.14,21.43 56.51,20.79 56.51,10.63 58.41,8.73 IC12.13 | v76.2,70.95 76.2,42.38 v73.02,39.2
  Bottom 0.254: v58.41,65.88 59.68,67.14 59.68,70.95 v60.95,70.95 v76.2,70.95 | v64.77,109.05 45.71,109.05 43.81,107.15 IC15.9 | IC19.2 16.51,40.48 17.78,39.2 v57.14,39.2 v73.02,39.2 76.83,35.4 77.47,35.4 IC17.18
DIO04  (via drill 0.61)
  Top 0.254: v73.66,93.18 73.66,97.62 IC13.2 | v26.67,62.7 26.67,65.88 24.12,65.88 IC18.17 | v67.94,42.38 67.94,60.16 69.21,61.43 | 69.21,61.43 70.48,62.7 IC16.3 | 69.21,61.43 v69.21,90.64
  Bottom 0.254: 69.21,93.18 v73.66,93.18 | 69.21,93.18 57.78,93.18 56.51,91.91 IC9.21 | v26.67,62.7 27.3,63.34 69.84,63.34 IC16.3 | v67.94,42.38 57.78,42.38 55.88,44.29 IC11.21 | v69.21,90.64 69.21,93.18
DIO05  (via drill 0.61)
  Top 0.254: IC13.1 71.12,97.62 v71.12,89.37 71.75,88.73 71.75,70.32 73.02,69.05 73.02,60.16 71.75,58.89 IC16.5 | IC18.15 24.12,60.8 v26.67,58.26 v26.67,48.09
  Bottom 0.254: v71.12,89.37 60.32,89.37 59.05,90.64 IC9.20 | v26.67,58.26 69.84,58.26 IC16.5 | v26.67,48.09 57.14,48.09 58.41,46.83 IC11.20
DIO06  (via drill 0.61)
  Top 0.254: 72.39,104.61 73.02,104.61 73.02,105.88 IC13.13 | 72.39,104.61 70.48,104.61 69.84,105.24 69.84,110.32 64.77,110.32 62.22,107.78 62.22,105.24 59.68,102.7 59.68,93.81 60.95,92.54 IC9.19 | v69.21,46.83 69.21,51.27 70.48,52.54 IC16.7 71.75,53.81 74.93,56.98 74.93,69.68 72.39,72.22 72.39,104.61 | v25.39,49.37 25.39,53.18 23.49,55.08 IC18.13
  Bottom 0.254: v69.21,46.83 68.58,47.46 62.86,47.46 61.59,46.19 IC11.19 60.32,46.19 57.14,49.37 v25.39,49.37
DIO07  (via drill 0.61)
  Top 0.254: 64.77,100.8 v64.77,103.34 | 64.77,100.8 64.77,93.81 63.49,92.54 IC9.18 | v63.49,50.63 63.49,46.83 IC11.18 | v67.31,100.8 64.77,100.8 | v69.21,98.89 69.84,98.26 69.84,91.27 70.48,90.64 70.48,90 69.84,89.37 69.84,77.3 v70.48,76.67 | v73.66,75.4 74.93,74.13 74.93,70.95 75.56,70.32 75.56,52.54 71.75,48.73 IC16.9
  Bottom 0.254: v64.77,103.34 66.04,104.61 74.29,104.61 75.56,105.88 IC13.12 | IC18.11 24.12,50.63 v63.49,50.63 67.31,50.63 69.84,48.09 IC16.9 | v69.21,98.89 v67.31,100.8 | v70.48,76.67 71.75,75.4 v73.66,75.4
DIO08  (via drill 0.61)
  Top 0.254: 78.73,85.56 78.73,96.35 77.47,97.62 77.47,103.97 78.73,105.24 IC13.11 | 78.73,85.56 78.73,70.95 80.64,69.05 80.64,50 79.37,48.73 IC16.12 | IC11.17 66.04,46.83 64.77,48.09 v64.77,85.56 64.77,88.73 66.04,90 IC9.17 | v18.41,45.55 v18.41,55.72 | v77.47,85.56 78.73,85.56
  Bottom 0.254: v18.41,55.72 16.51,55.72 IC18.8 | v18.41,45.55 19.68,46.83 26.67,46.83 27.3,47.46 56.51,47.46 57.14,46.83 57.14,44.29 57.78,43.65 64.13,43.65 65.4,44.92 IC11.17 | v64.77,85.56 v77.47,85.56
DIO09  (via drill 0.61)
  Top 0.254: IC9.15 63.49,74.77 63.49,72.22 62.22,70.95 v62.22,59.52 v62.22,55.08 62.22,32.86 63.49,31.59 IC11.15 | v80.01,78.57 80.01,100.16 80.64,100.8 80.64,104.61 81.28,105.24 IC13.10
  Bottom 0.254: v62.22,59.52 17.78,59.52 16.51,60.8 IC18.6 | v62.22,55.08 66.67,55.08 67.31,54.45 76.2,54.45 77.47,53.18 IC16.14 | v80.01,78.57 79.37,77.94 65.4,77.94 64.13,76.67 IC9.15
DIO10  (via drill 0.61)
  Top 0.254: IC11.14 60.95,31.59 59.68,32.86 v59.68,60.8 59.68,73.49 60.95,74.77 IC9.14 60.95,77.3 v60.95,83.02 | v24.76,64.6 25.39,63.97 v25.39,62.06 | v71.12,103.34 67.94,100.16 v67.94,83.02
  Bottom 0.254: IC16.16 77.47,58.26 76.2,59.52 63.49,59.52 62.22,60.8 v59.68,60.8 26.67,60.8 v25.39,62.06 | v24.76,64.6 17.78,64.6 16.51,65.88 IC18.4 | v71.12,103.34 80.64,103.34 83.18,105.88 IC13.9 | v60.95,83.02 v67.94,83.02
DIO11  (via drill 0.61)
  Top 0.254: IC9.13 58.41,74.77 v58.41,72.22 58.41,70.95 57.14,69.68 57.14,67.14 55.88,65.88 v55.88,62.06 55.88,55.72 57.14,54.45 57.14,44.29 58.41,43.02 58.41,31.59 IC11.13 | v85.09,72.22 85.09,103.97 86.36,105.24 IC13.8
  Bottom 0.254: IC18.2 16.51,70.95 17.78,72.22 v58.41,72.22 60.95,72.22 61.59,71.59 66.04,71.59 66.67,72.22 v85.09,72.22 | v55.88,62.06 72.39,62.06 73.02,62.7 76.83,62.7 77.47,63.34 IC16.18
DIOEVEN  (via drill 0.61)
  Top 0.254: v20.95,105.24 v20.95,62.06 20.95,50 24.76,46.19 24.76,26.51 v26.03,25.23
  Bottom 0.254: IC17.9 69.84,20.16 66.04,20.16 64.13,22.06 IC12.18 62.86,23.33 60.95,25.23 v26.03,25.23 | v20.95,62.06 24.12,62.06 26.03,63.97 63.49,63.97 63.49,67.14 IC10.18 | v20.95,105.24 29.21,105.24 29.84,104.61 31.11,104.61 32.38,105.88 IC15.13
DMA00  (via drill 0.61)
  Top 0.254: IC9.25 45.71,90 46.98,88.73 46.98,74.77 46.35,74.13 46.35,70.32 45.71,69.68 IC10.25 45.71,67.14 46.35,66.51 46.35,55.08 46.98,54.45 46.98,50.63 45.71,49.37 45.71,46.83 IC11.25 46.35,44.92 46.35,32.22 46.98,31.59 46.98,29.05 46.35,28.41 46.35,24.6 45.71,23.96 IC12.25 45.71,21.43 45.71,10 46.98,8.73 v46.98,5.55 | v147.95,16.35 147.95,11.9 149.22,10.63 IC8.8 | v140.97,12.54 v140.97,16.35
  Bottom 0.254: v46.98,5.55 66.67,5.55 67.94,6.82 82.55,6.82 83.81,8.09 122.55,8.09 123.19,7.46 DMA0-3.7 125.73,7.46 129.53,11.27 139.69,11.27 v140.97,12.54 | v140.97,16.35 v147.95,16.35
DMA01  (via drill 0.61)
  Top 0.254: IC9.23 50.79,90 52.06,88.73 52.06,74.77 51.43,74.13 51.43,69.05 IC10.23 50.79,67.14 51.43,66.51 51.43,55.08 52.06,54.45 52.06,48.09 50.79,46.83 IC11.23 50.79,44.29 50.79,32.86 52.06,31.59 52.06,25.23 50.79,23.96 IC12.23 51.43,22.06 51.43,9.36 52.06,8.73 52.06,6.18 v55.24,3.01 | v121.92,2.38 121.92,7.46 123.82,9.36 DMA0-3.6
  Bottom 0.254: DMA0-3.6 125.73,10 129.53,13.81 147.31,13.81 148.59,15.08 IC8.6 | v121.92,2.38 121.28,1.74 79.37,1.74 77.47,3.65 76.2,2.38 55.88,2.38 v55.24,3.01
DMA02  (via drill 0.61)
  Top 0.254: v151.76,26.51 151.76,22.06 150.49,20.79 IC8.4 | IC12.26 43.17,23.96 44.45,25.23 v44.45,27.78 44.45,32.22 43.17,33.49 43.17,44.29 IC11.26 43.81,46.19 43.81,51.27 44.45,51.91 44.45,65.88 43.17,67.14 IC10.26 43.81,69.05 43.81,74.13 44.45,74.77 44.45,77.3 42.54,79.21 42.54,89.37 43.17,90 IC9.26
  Bottom 0.254: v151.76,26.51 148.59,26.51 146.05,23.96 129.53,23.96 125.73,20.16 DMA0-3.2 123.19,20.16 122.55,20.79 118.11,20.79 117.47,21.43 92.07,21.43 86.99,26.51 63.49,26.51 62.22,27.78 v44.45,27.78
DMA03  (via drill 0.61)
  Top 0.254: v128.27,17.62 129.53,16.35 129.53,10 130.81,8.73 133.34,8.73 135.25,6.82 135.25,4.28 135.88,3.65 146.68,3.65 146.68,22.06 149.22,24.6 IC8.2 | IC12.27 40.63,23.96 41.9,25.23 41.9,43.02 40.63,44.29 IC11.27 40.63,46.83 41.9,48.09 41.9,54.45 40.63,55.72 40.63,67.14 IC10.27 40.63,69.68 41.9,70.95 41.9,88.73 40.63,90 IC9.27 | v82.55,23.96 81.28,25.23 81.28,32.86 80.01,34.12 76.83,34.12 76.83,70.32 77.47,70.95 77.47,74.77 73.66,78.57 v73.66,88.1
  Bottom 0.254: v128.27,17.62 125.73,17.62 DMA0-3.3 123.19,17.62 122.55,18.25 92.7,18.25 86.99,23.96 v82.55,23.96 | v73.66,88.1 43.81,88.1 41.27,90.64 IC9.27
DMA04  (via drill 0.61)
  Top 0.254: v127.63,32.22 127.63,34.76 125.09,37.3 DMA4-7.7 | v147.95,31.59 147.95,38.57 149.22,39.84 IC7.8 | IC12.5 38.09,8.73 36.82,10 36.82,23.96 38.09,25.23 38.09,29.05 IC11.5 38.09,31.59 36.82,32.86 36.82,46.83 38.09,48.09 38.09,51.91 IC10.5 38.09,54.45 36.82,55.72 36.82,69.68 38.09,70.95 38.09,74.77 IC9.5 | v97.79,39.2 97.79,6.18 93.34,1.74 77.47,1.74 v77.47,2.38
  Bottom 0.254: v127.63,32.22 129.53,30.32 142.87,30.32 144.78,32.22 147.31,32.22 v147.95,31.59 | v97.79,39.2 121.92,39.2 123.19,37.94 DMA4-7.7 | v77.47,2.38 76.83,1.74 43.81,1.74 38.73,6.82 IC12.5
DMA05  (via drill 0.61)
  Top 0.254: IC12.6 40.63,8.73 39.36,10 39.36,23.96 40.63,25.23 40.63,29.05 IC11.6 40.63,31.59 40,32.22 40,43.65 39.36,44.29 39.36,46.83 40.63,48.09 40.63,51.91 IC10.6 40.63,54.45 40,55.08 40,66.51 39.36,67.14 39.36,69.68 40.63,70.95 40.63,74.77 IC9.6 | v121.28,40.48 120.01,39.2 120.01,26.51 120.65,25.87 120.65,13.81 v119.38,12.54 | v66.04,3.65 v70.48,8.09
  Bottom 0.254: IC7.6 148.59,45.55 147.31,44.29 135.88,44.29 133.34,41.74 127,41.74 125.73,40.48 DMA4-7.6 123.19,40.48 v121.28,40.48 | v119.38,12.54 115.56,8.73 83.18,8.73 82.55,9.36 71.75,9.36 v70.48,8.09 | v66.04,3.65 65.4,4.28 48.25,4.28 47.62,3.65 44.45,3.65 41.27,6.82 IC12.6
DMA06  (via drill 0.61)
  Top 0.254: IC12.7 43.17,8.73 41.9,10 41.9,23.96 43.17,25.23 43.17,29.05 IC11.7 43.17,31.59 42.54,32.22 42.54,43.65 41.9,44.29 41.9,46.83 43.17,48.09 43.17,51.91 IC10.7 43.17,54.45 41.9,55.72 41.9,69.68 43.17,70.95 43.17,74.77 IC9.7 | v139.06,46.83 139.06,34.76 137.16,32.86 134.62,32.86 v134.62,8.73 | v129.53,8.73 128.9,8.09 128.9,6.82 v125.09,3.01 | v82.55,8.09 v82.55,3.01 | v68.58,4.92 v71.75,8.09
  Bottom 0.254: 139.06,49.37 147.31,49.37 148.59,50.63 IC7.4 | 139.06,49.37 127,49.37 125.73,50.63 DMA4-7.2 | v139.06,46.83 139.06,49.37 | v129.53,8.73 v134.62,8.73 | v125.09,3.01 124.45,3.65 95.25,3.65 94.61,3.01 v82.55,3.01 | v71.75,8.09 v82.55,8.09 | v68.58,4.92 47.62,4.92 46.98,4.28 46.35,4.28 43.81,6.82 IC12.7
DMA07  (via drill 0.61)
  Top 0.254: DMA4-7.3 125.09,48.73 126.36,50 v126.36,56.98 v126.36,62.7 | IC12.8 45.71,8.73 44.45,10 44.45,23.96 45.71,25.23 45.71,29.05 IC11.8 45.71,31.59 45.71,32.22 44.45,33.49 44.45,50.63 45.71,51.91 IC10.8 45.71,54.45 45.71,65.88 44.45,67.14 44.45,73.49 45.71,74.77 IC9.8 | v95.25,77.94 v95.25,70.32 | v54.6,81.75 v54.6,78.57
  Bottom 0.254: v126.36,56.98 144.14,56.98 145.41,55.72 148.59,55.72 IC7.2 | v126.36,62.7 124.45,64.6 110.48,64.6 109.22,65.88 96.52,65.88 95.25,67.14 v95.25,70.32 | v95.25,77.94 93.34,79.84 57.78,79.84 56.51,78.57 v54.6,78.57 | v54.6,81.75 51.43,81.75 46.35,76.67 IC9.8
DMA08  (via drill 0.61)
  Top 0.254: IC12.9 48.25,8.73 46.98,10 46.98,27.78 48.25,29.05 IC11.9 48.25,31.59 46.98,32.86 46.98,49.37 48.25,50.63 48.25,51.91 IC10.9 48.25,54.45 46.98,55.72 46.98,73.49 48.25,74.77 IC9.9 | v73.66,58.26 v73.66,69.68
  Bottom 0.254: IC6.8 148.59,70.95 147.31,70.95 146.05,72.22 135.88,72.22 133.34,69.68 130.81,69.68 130.17,69.05 126.36,69.05 125.73,68.41 DMA8-11.7 123.19,68.41 121.92,67.14 110.48,67.14 109.85,66.51 98.42,66.51 97.79,67.14 97.79,71.59 85.72,71.59 85.09,70.95 77.47,70.95 76.2,69.68 v73.66,69.68 | v73.66,58.26 72.39,56.98 52.06,56.98 48.89,53.81 IC10.9
DMA09  (via drill 0.61)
